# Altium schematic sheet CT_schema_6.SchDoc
size 479 x 328 mm
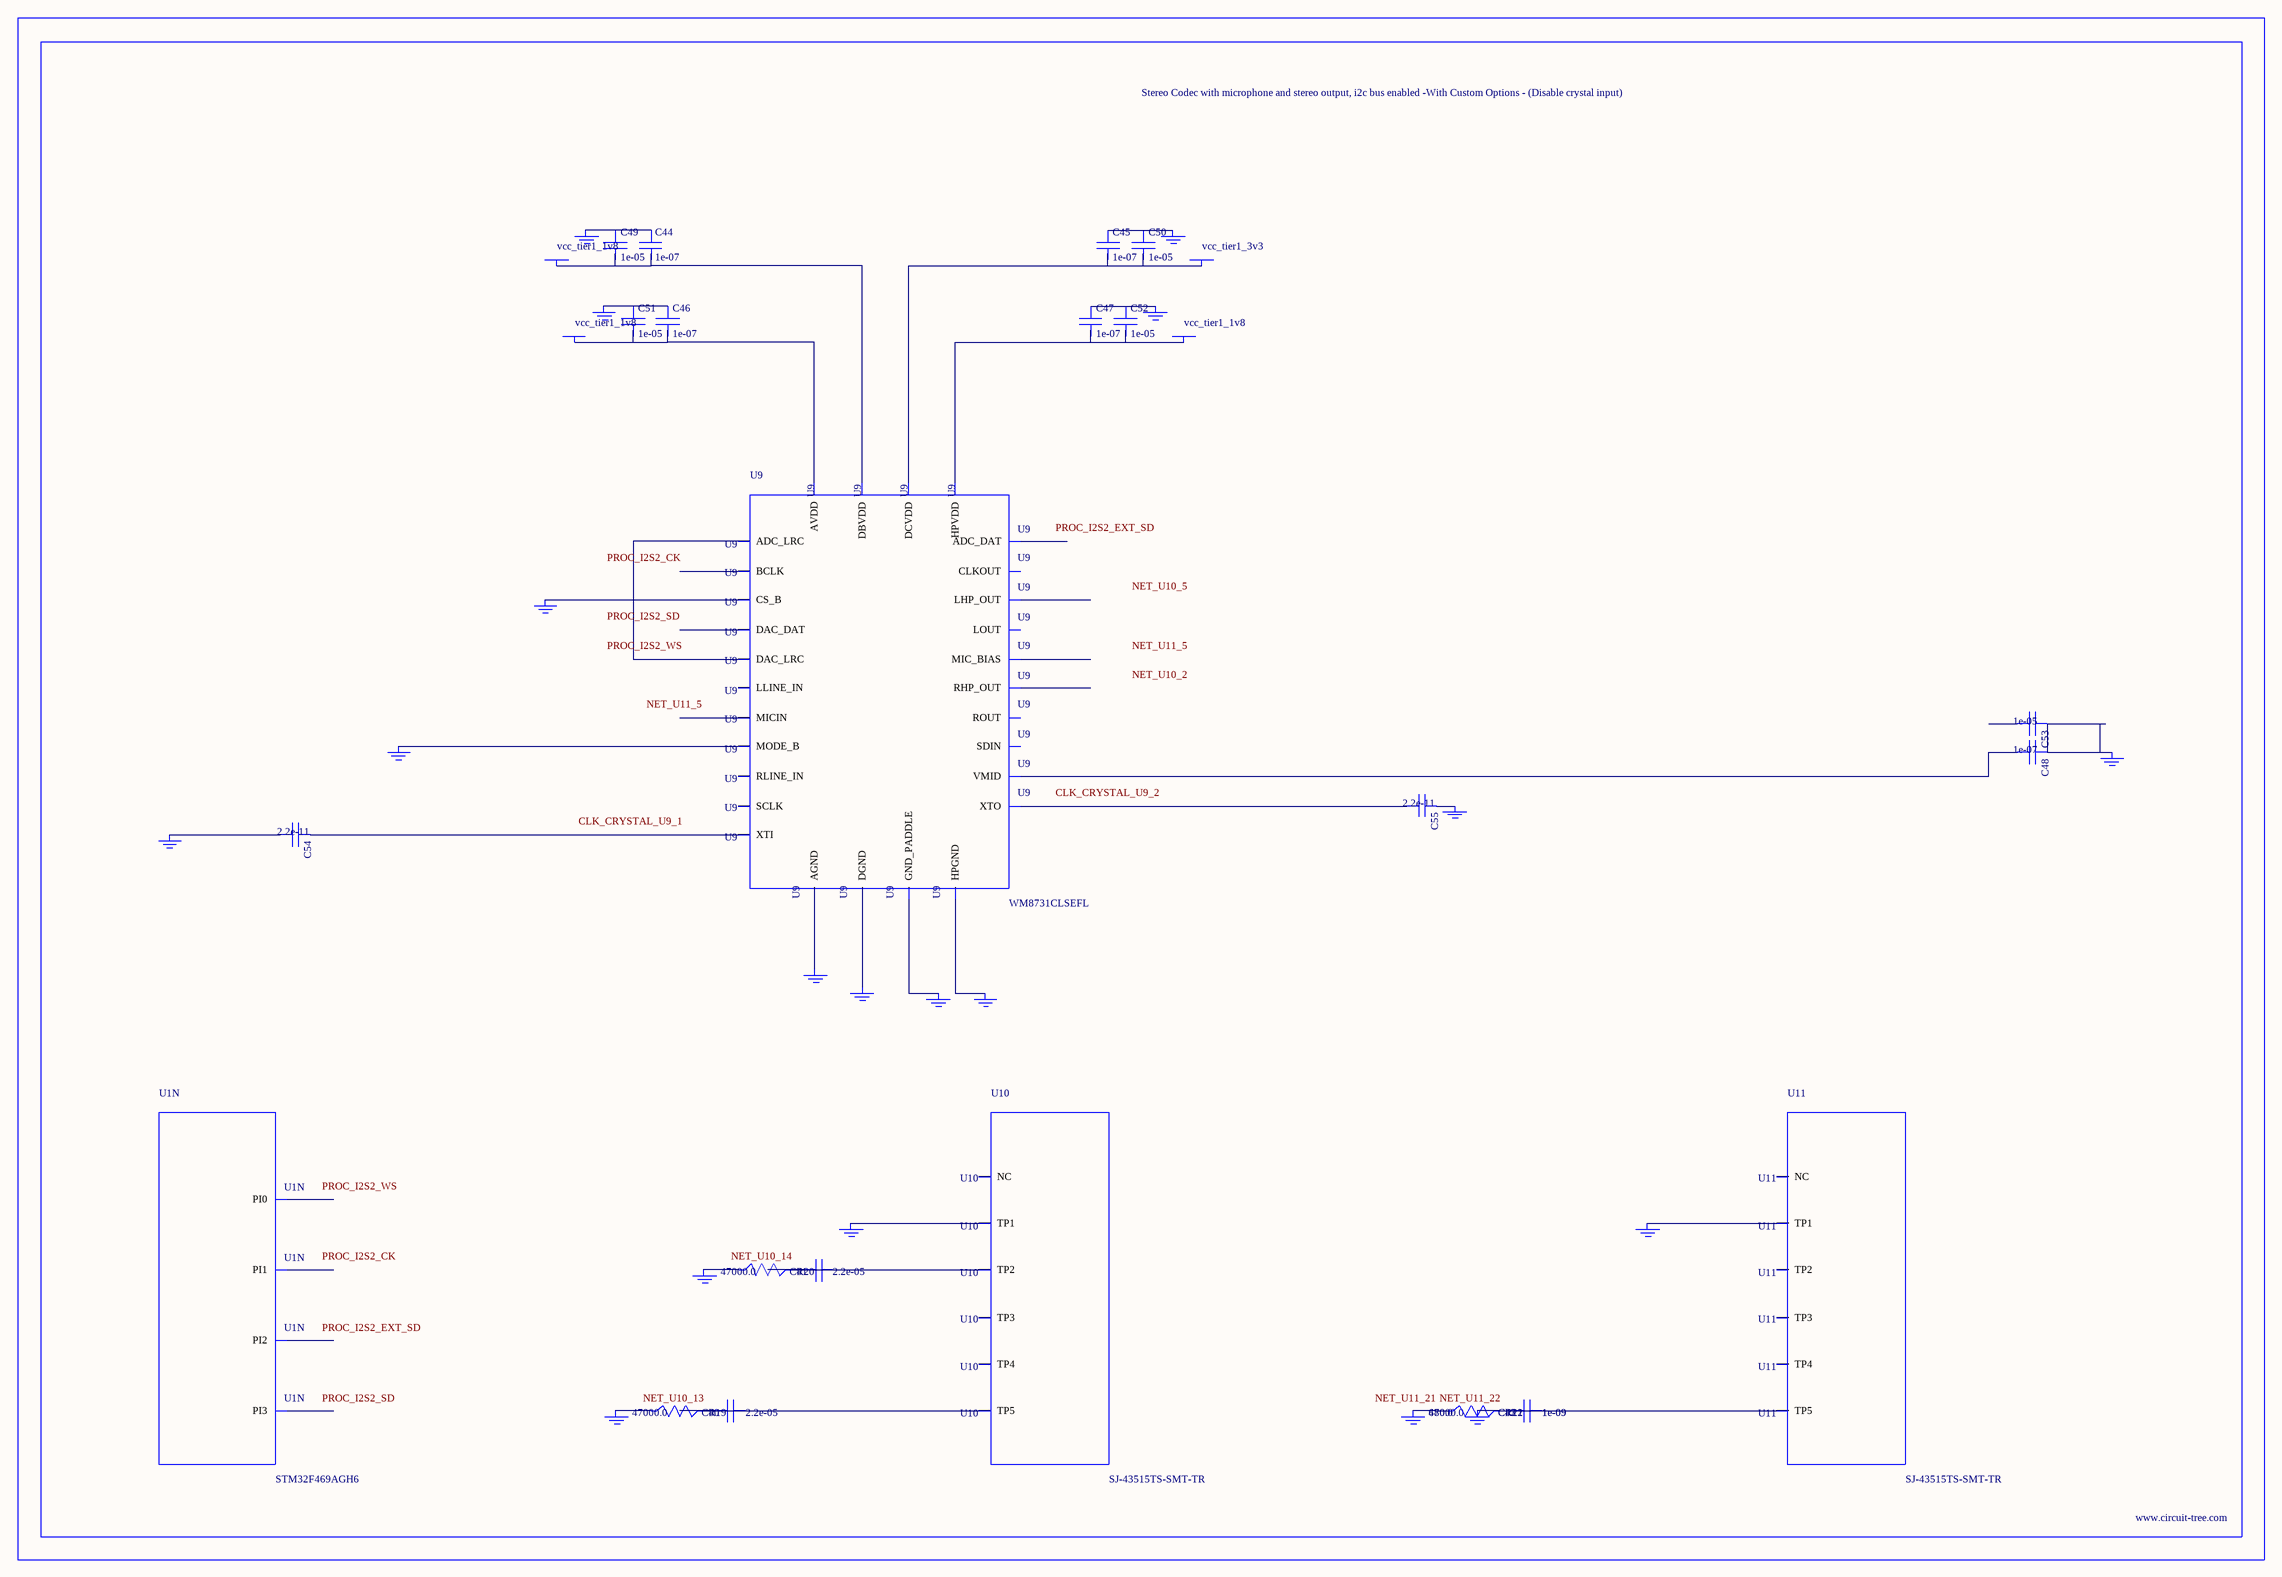
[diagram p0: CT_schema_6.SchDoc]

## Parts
BORDER5  (no value)
C40  2.2e-05  [C1210]
C41  2.2e-05  [C1210]
C42  1e-09  [C0402]
C43  1e-09  [C0402]
C44  1e-07  [C0402]
C45  1e-07  [C0402]
C46  1e-07  [C0402]
C47  1e-07  [C0402]
C48  1e-07  [C0402]
C49  1e-05  [C0805]
C50  1e-05  [C0805]
C51  1e-05  [C0805]
C52  1e-05  [C0805]
C53  1e-05  [C0805]
C54  2.2e-11  [C0402]
C55  2.2e-11  [C0402]
GND_INSTANCE_5_0  (no value)
GND_INSTANCE_5_1  (no value)
GND_INSTANCE_5_2  (no value)
GND_INSTANCE_5_3  (no value)
GND_INSTANCE_5_4  (no value)
GND_INSTANCE_5_5  (no value)
GND_INSTANCE_5_6  (no value)
GND_INSTANCE_5_7  (no value)
GND_INSTANCE_5_8  (no value)
GND_INSTANCE_5_9  (no value)
GND_INSTANCE_5_10  (no value)
GND_INSTANCE_5_11  (no value)
GND_INSTANCE_5_12  (no value)
GND_INSTANCE_5_13  (no value)
GND_INSTANCE_5_14  (no value)
GND_INSTANCE_5_15  (no value)
GND_INSTANCE_5_16  (no value)
GND_INSTANCE_5_17  (no value)
GND_INSTANCE_5_18  (no value)
POWER_INSTANCE_5_0  vcc_tier1_3v3
POWER_INSTANCE_5_1  vcc_tier1_1v8
POWER_INSTANCE_5_2  vcc_tier1_1v8
POWER_INSTANCE_5_3  vcc_tier1_1v8
R19  47000.0  [R0603]
R20  47000.0  [R0603]
R21  47000.0  [R0603]
R22  680.0  [R0603]
U1  STM32F469AGH6  [UFBGA169]  (part N of 14)
U9  WM8731CLSEFL  [QFN-28]
U10  SJ-43515TS-SMT-TR  [SJ-43515TS-SMT-TR]
U11  SJ-43515TS-SMT-TR  [SJ-43515TS-SMT-TR]

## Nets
NetC40_1: C40.1 C40.2 R19.2 U10.5(TP5)
NetC41_1: C41.1 C41.2 R20.2 U10.2(TP2)
NetC42_1: C42.1 C42.2 C43.1 C43.2 GND_INSTANCE_5_18.0(GND) R21.2 R22.2 U11.5(TP5)
NetC44_1: C44.1 C49.1 GND_INSTANCE_5_3.0(GND)
NetC44_2: C44.2 C49.2 POWER_INSTANCE_5_1.0(PWR) U9.5(DBVDD)
NetC45_1: C45.1 C50.1 GND_INSTANCE_5_2.0(GND)
NetC45_2: C45.2 C50.2 POWER_INSTANCE_5_0.0(PWR) U9.3(DCVDD)
NetC46_1: C46.1 C51.1 GND_INSTANCE_5_6.0(GND)
NetC46_2: C46.2 C51.2 POWER_INSTANCE_5_3.0(PWR) U9.18(AVDD)
NetC47_1: C47.1 C52.1 GND_INSTANCE_5_4.0(GND)
NetC47_2: C47.2 C52.2 POWER_INSTANCE_5_2.0(PWR) U9.12(HPVDD)
NetC48_1: C48.1 C53.1 GND_INSTANCE_5_7.0(GND)
NetC48_2: C48.2 U9.20(VMID)
NetC54_1: C54.1 U9.1(XTI)
NetC54_2: C54.2 GND_INSTANCE_5_0.0(GND)
NetC55_1: C55.1 GND_INSTANCE_5_1.0(GND)
NetC55_2: C55.2 U9.2(XTO)
NetGND_INSTANCE_5_5_0: GND_INSTANCE_5_5.0(GND) U9.15(HPGND)
NetGND_INSTANCE_5_8_0: GND_INSTANCE_5_8.0(GND) U9.25(MODE_B)
NetGND_INSTANCE_5_9_0: GND_INSTANCE_5_9.0(GND) U9.26(CS_B)
NetGND_INSTANCE_5_10_0: GND_INSTANCE_5_10.0(GND) U9.29(GND_PADDLE)
NetGND_INSTANCE_5_11_0: GND_INSTANCE_5_11.0(GND) U9.4(DGND)
NetGND_INSTANCE_5_12_0: GND_INSTANCE_5_12.0(GND) U9.19(AGND)
NetGND_INSTANCE_5_13_0: GND_INSTANCE_5_13.0(GND) U10.1(TP1)
NetGND_INSTANCE_5_14_0: GND_INSTANCE_5_14.0(GND) R20.1
NetGND_INSTANCE_5_15_0: GND_INSTANCE_5_15.0(GND) R19.1
NetGND_INSTANCE_5_16_0: GND_INSTANCE_5_16.0(GND) U11.1(TP1)
NetGND_INSTANCE_5_17_0: GND_INSTANCE_5_17.0(GND) R21.1 R22.1
NetU9_9: U9.9(DAC_LRC) U9.11(ADC_LRC)

Not connected (* = marked no-connect by the designer): C53 2; U1 B10(PI3) B12(PI2) B13(PI0) C11(PI1); U9 6(CLKOUT) 7(BCLK) 8(DAC_DAT) 10(ADC_DAT) 13(LHP_OUT) 14(RHP_OUT) 16(LOUT) 17(ROUT) 21(MIC_BIAS) 22(MICIN) 23(RLINE_IN) 24(LLINE_IN) 27(SDIN) 28(SCLK); U10 3(TP3) 4(TP4) 6(NC); U11 2(TP2) 3(TP3) 4(TP4) 6(NC)

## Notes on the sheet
- Labels drawn without touching a wire or pin: CLK_CRYSTAL_U9_1, CLK_CRYSTAL_U9_2, NET_U10_2, NET_U10_5, NET_U10_13, NET_U10_14, NET_U11_5, NET_U11_21, NET_U11_22, PROC_I2S2_CK, PROC_I2S2_EXT_SD, PROC_I2S2_SD, PROC_I2S2_WS

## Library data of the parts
BORDER5 = BORDER_PAGE5
C40 C41 = C1210C224K5RACTU
C42 C43 = C0402C102K3RAC
C44-C48 = C0402C104K3RACTU
C49-C53 = C0805C106K8RACTU
C54 C55 = C0402C220K3RAC
GND_INSTANCE_5_0-GND_INSTANCE_5_18 = GND
POWER_INSTANCE_5_0-POWER_INSTANCE_5_3 = PWR
R19-R21 = RC0603JR-0747KL
R22 = RC0603JR-07680RL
